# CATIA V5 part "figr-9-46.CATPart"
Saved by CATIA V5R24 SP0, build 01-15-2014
Part number: Part1
Bounding box of the stored display mesh (mm): x -159.661 to 182.627, y -78.048 to 78.048, z 0 to 72.429
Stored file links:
  D:\KAVITA\CATIA V5-6R2014 Project_ Kavita\CATIA V5-6R2014_partfiles\Partfiles\c09_catia_v5-6r2014_prt\figr-9-46.CATPart
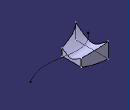
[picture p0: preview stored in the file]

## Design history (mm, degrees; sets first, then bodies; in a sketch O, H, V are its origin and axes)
Body1 (main body)
  Plane1: type Offset, RefPlane yz-plane, Offset 100
  Plane2: type Offset, RefPlane yz-plane, Offset 100, reversed
  Sketch1 on Plane1, origin (100, 0, 0), H (0, 1, 0), V (0, 0, 1)
    point P1 (0, 15.965)
    hyperbola C1
    point P2 (0, 3.0416)
    line L1 (54.8261, 44.8858) -> (54.8261, 0)
    point P5 (54.8261, 0)
    line L2 (-54.8261, 44.8858) -> (-54.8261, 0)
    point P6 (-54.8261, 0)
    line L3 (-54.8261, 0) -> (54.8261, 0)
    coincidence: P1 V, P2 V, P5 H, P6 H
    vertical: L1 V, L2 V
    horizontal: L3 H
  Sketch2 on xy-plane, origin (0, 0, 0), H (1, 0, 0), V (0, 1, 0)
    spline S1 through (-159.6608, -77.1468) (-77.8466, -31.8169) (23.6283, -41.4968) (182.6271, -11.7333)
  Sketch3 on yz-plane, origin (0, 0, 0), H (0, 1, 0), V (0, 0, 1)
    point P1 (0, 18.9787)
    hyperbola C1
    point P2 (0, 2.6681)
    line L1 (48.2237, 37.1764) -> (48.2237, 0)
    point P5 (48.2237, 0)
    line L2 (-43.6563, 34.1546) -> (-43.6563, 0)
    point P6 (-43.6563, 0)
    line L3 (-43.6563, 0) -> (48.2237, 0)
    coincidence: P1 V, P2 V, P5 H, P6 H
    vertical: L1 V, L2 V
    horizontal: L3 H
  Sketch4 on Plane2, origin (-100, 0, 0), H (0, 1, 0), V (0, 0, 1)
    point P1 (0, 140.6052)
    point P2 (0, 41.8972)
    hyperbola C1
    line L1 (78.0478, 72.4293) -> (78.0478, 0)
    point P5 (78.0478, 0)
    line L2 (-78.0478, 72.4293) -> (-78.0478, 0)
    point P6 (-78.0478, 0)
    line L3 (-78.0478, 0) -> (78.0478, 0)
    coincidence: P1 V, P2 V, P5 H, P6 H
    vertical: L1 V, L2 V
    horizontal: L3 H
  Loft1: solid, Sections (Sketch3; Sketch4), Spine Sketch2
  Loft2: solid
